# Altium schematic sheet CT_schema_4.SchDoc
size 284 x 147 mm
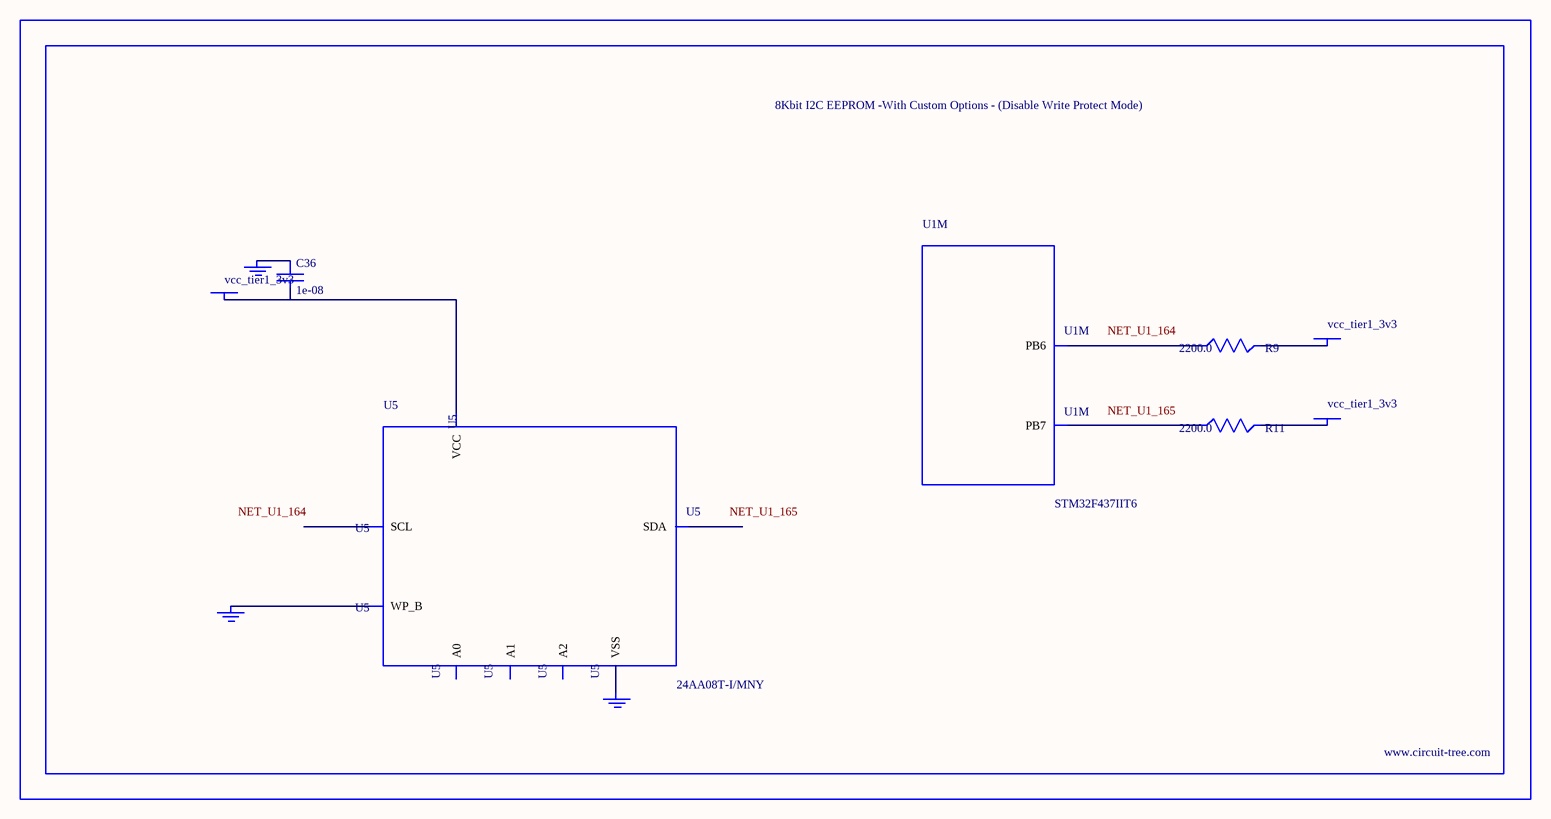
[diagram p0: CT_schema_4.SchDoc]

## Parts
BORDER3  (no value)
C36  1e-08  [C0402]
GND_INSTANCE_3_0  (no value)
GND_INSTANCE_3_1  (no value)
GND_INSTANCE_3_2  (no value)
POWER_INSTANCE_3_0  vcc_tier1_3v3
POWER_INSTANCE_3_1  vcc_tier1_3v3
POWER_INSTANCE_3_2  vcc_tier1_3v3
R9  2200.0  [R0603]
R11  2200.0  [R0603]
U1  STM32F437IIT6  [LQFP176]  (part M of 16)
U5  24AA08T-I/MNY  [TDFN-8/6MM]

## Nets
NetC36_1: C36.1 GND_INSTANCE_3_1.0(GND)
NetC36_2: C36.2 POWER_INSTANCE_3_0.0(PWR) U5.8(VCC)
NetGND_INSTANCE_3_0_0: GND_INSTANCE_3_0.0(GND) U5.7(WP_B)
NetGND_INSTANCE_3_2_0: GND_INSTANCE_3_2.0(GND) U5.4(VSS)
NetPOWER_INSTANCE_3_1_0: POWER_INSTANCE_3_1.0(PWR) R9.2
NetPOWER_INSTANCE_3_2_0: POWER_INSTANCE_3_2.0(PWR) R11.2
NetR9_1: R9.1 U1.164(PB6)
NetR11_1: R11.1 U1.165(PB7)

Not connected (* = marked no-connect by the designer): U5 1(A0) 2(A1) 3(A2) 5(SDA) 6(SCL)

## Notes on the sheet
- Labels drawn without touching a wire or pin: NET_U1_164, NET_U1_165

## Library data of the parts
BORDER3 = BORDER_PAGE3
C36 = C0402C103K3RAC
GND_INSTANCE_3_0-GND_INSTANCE_3_2 = GND
POWER_INSTANCE_3_0-POWER_INSTANCE_3_2 = PWR
R9 R11 = RC0603JR-072K2L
